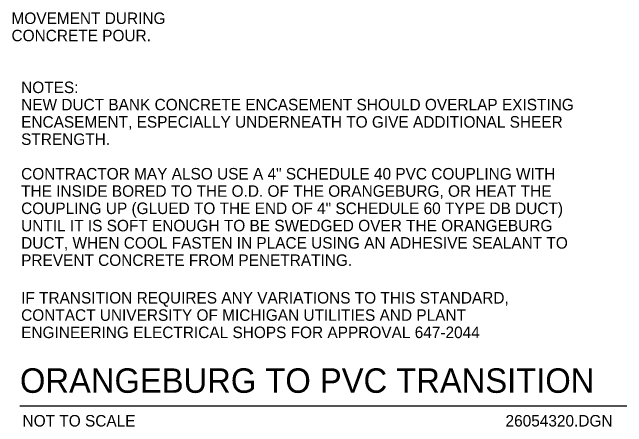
# Model space of a CAD drawing. Extents: x 10012.1 to 10048.7, y 9901.7 to 9957.2.
# Drawn here: x 10013.16 to 10048.74, y 9901.67 to 9925.65 of the extents above; entities that cross this region are included whole.
import ezdxf

# ---------------------------------------------------------------- set-up
doc = ezdxf.new("R2010")
doc.units = 0
doc.layers.add('Default', color=7, linetype='Continuous')
doc.layers.add('G-ANNO-TEXT', color=7, linetype='Continuous')

msp = doc.modelspace()

# ---------------------------------------------------------------- linework, layer by layer
at = {"layer": 'Default'}
msp.add_line((10013.604, 9902.887), (10048.737, 9902.887), dxfattribs=at)

# ---------------------------------------------------------------- texts
for s, height, p in [('ORANGEBURG TO PVC TRANSITION', 1.41667, (10013.604, 9903.63)), ('NOT TO SCALE', 0.66667, (10013.755, 9901.68)), ('26054320.DGN', 0.66667, (10041.721, 9901.68))]:
    msp.add_text(s, height=height, dxfattribs=at).set_placement(p)
at = {"layer": 'G-ANNO-TEXT'}
for s, height, p in [('MOVEMENT DURING', 0.66667, (10013.115, 9924.971)), ('CONCRETE POUR.', 0.66667, (10013.115, 9923.971)), ('NOTES:', 0.6667, (10013.673, 9920.973)), ('NEW DUCT BANK CONCRETE ENCASEMENT SHOULD OVERLAP EXISTING', 0.66667, (10013.673, 9919.973)), ('ENCASEMENT, ESPECIALLY UNDERNEATH TO GIVE ADDITIONAL SHEER', 0.66667, (10013.673, 9918.973)), ('STRENGTH.', 0.6667, (10013.673, 9917.973)), ('CONTRACTOR MAY ALSO USE A 4" SCHEDULE 40 PVC COUPLING WITH', 0.66667, (10013.673, 9915.973)), ('THE INSIDE BORED TO THE O.D. OF THE ORANGEBURG, OR HEAT THE', 0.66667, (10013.673, 9914.973)), ('COUPLING UP (GLUED TO THE END OF 4" SCHEDULE 60 TYPE DB DUCT)', 0.66667, (10013.673, 9913.973)), ('UNTIL IT IS SOFT ENOUGH TO BE SWEDGED OVER THE ORANGEBURG', 0.66667, (10013.673, 9912.973)), ('DUCT, WHEN COOL FASTEN IN PLACE USING AN ADHESIVE SEALANT TO', 0.66667, (10013.673, 9911.973)), ('PREVENT CONCRETE FROM PENETRATING.', 0.66667, (10013.673, 9910.973)), ('IF TRANSITION REQUIRES ANY VARIATIONS TO THIS STANDARD,', 0.66667, (10013.673, 9908.796)), ('CONTACT UNIVERSITY OF MICHIGAN UTILITIES AND PLANT', 0.66667, (10013.673, 9907.796)), ('ENGINEERING ELECTRICAL SHOPS FOR APPROVAL 647-2044', 0.66667, (10013.673, 9906.796))]:
    msp.add_text(s, height=height, dxfattribs=at).set_placement(p)

doc.saveas('drawing.dxf')
